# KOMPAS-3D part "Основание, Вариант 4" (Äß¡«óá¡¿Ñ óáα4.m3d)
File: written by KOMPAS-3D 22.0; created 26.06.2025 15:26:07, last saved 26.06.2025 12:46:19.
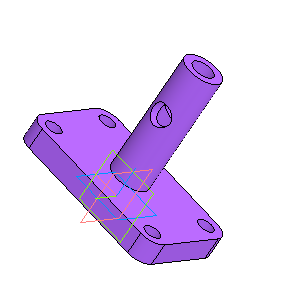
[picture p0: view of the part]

Document properties: Автор: Helen; Полное имя файла: D:\MY\WORK\MPEI\ППЭ_2025-2026\Варианты\Вар 4 СБ\Основание вар4.m3d

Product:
- Body: Тело 1
    Масса: 2.725967
- Part/product: Основание  | designation Вариант 4
    Масса: 2.685762

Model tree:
1. Эскиз:1
2. Элемент выдавливания:1
     Расстояние 1 = 20
3. Эскиз:3  (with: Элемент выдавливания:1)
4. Элемент выдавливания:3
     Расстояние 2 = 20
5. Массив по сетке:1  (with: Элемент выдавливания:3, Эскиз:3, Элемент выдавливания:1)  (4 pattern instances)
     Шаг 1 = 120; Угол раствора = 90; Шаг 2 = 70
6. Эскиз:4  (with: Элемент выдавливания:1)
7. Элемент выдавливания:4
     Расстояние 1 = 110
8. Эскиз:6  (with: Элемент выдавливания:1)
9. Элемент выдавливания:8
     Расстояние 2 = 130
10. Эскиз:7
11. Элемент выдавливания:9
     Расстояние 1 = 50

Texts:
  Вариант 4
